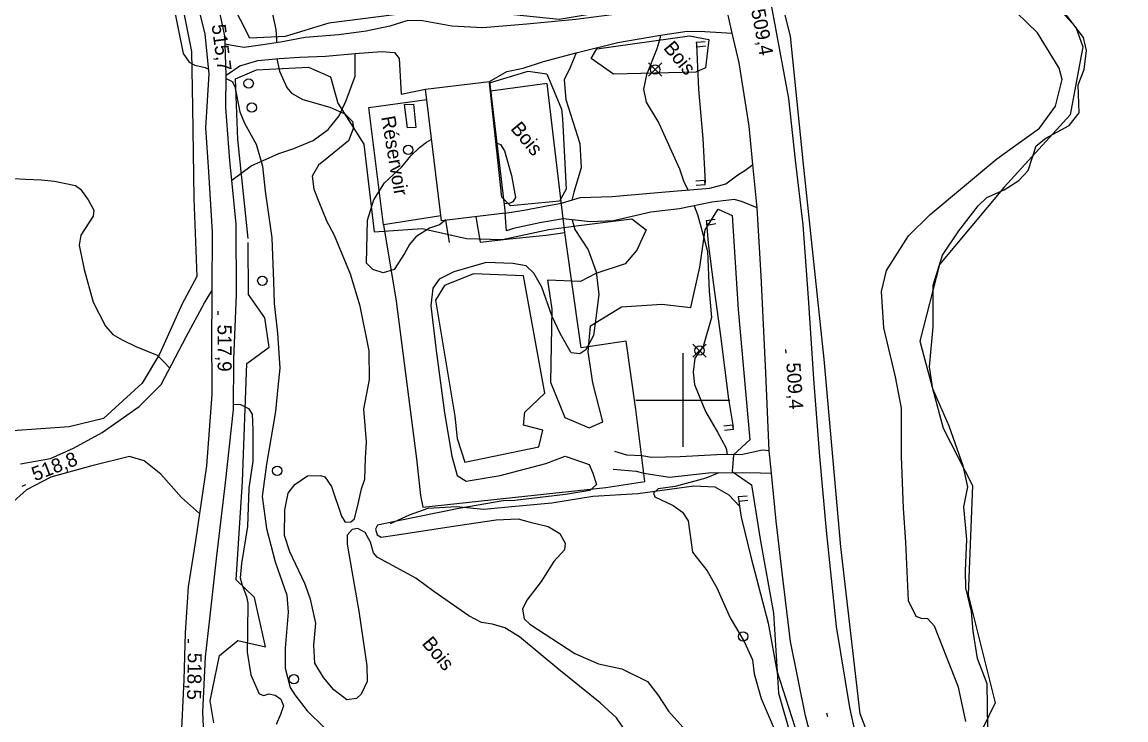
# Model space of a CAD drawing. Extents: x 347312 to 350503, y 6073086 to 6076432.
# Drawn here: x 347759 to 347994.5, y 6075331.8 to 6075480.7 of the extents above; entities that cross this region are included whole.
import ezdxf

# ---------------------------------------------------------------- set-up
doc = ezdxf.new("R2010")
doc.units = 0
for name, color, linetype in [('Level 1', 7, 'Continuous'), ('Level 19', 7, 'Continuous'), ('Level 2', 7, 'Continuous'), ('Level 21', 7, 'Continuous'), ('Level 22', 7, 'Continuous'), ('Level 26', 7, 'Continuous'), ('Level 3', 7, 'Continuous'), ('Level 31', 7, 'Continuous'), ('Level 33', 7, 'Continuous'), ('Level 36', 7, 'Continuous'), ('Level 37', 7, 'Continuous'), ('Level 4', 7, 'Continuous'), ('Level 44', 7, 'Continuous'), ('Level 61', 7, 'Continuous')]:
    doc.layers.add(name, color=color, linetype=linetype)

msp = doc.modelspace()

# ---------------------------------------------------------------- linework, layer by layer
at = {"layer": 'Level 1'}
for points in [[(347895.24, 6075477.89), (347895.1, 6075477.1), (347894.43, 6075474.95), (347892.21, 6075469.37), (347891.63, 6075466.35), (347892.18, 6075463.58), (347894.84, 6075459.07), (347899.29, 6075449.32), (347900.16, 6075446.81), (347901.05, 6075444.85)], [(347902.42, 6075441.44), (347903.12, 6075439.57), (347904.11, 6075435.94), (347905.26, 6075431.69), (347905.6, 6075423.24), (347906.08, 6075417.64), (347904.33, 6075411.47), (347902.54, 6075408.93), (347902.18, 6075405.96), (347902.45, 6075403.36), (347904.85, 6075397.55), (347907.38, 6075393.19), (347909.27, 6075389.78), (347909.42, 6075388.37)], [(347907.65, 6075384.47), (347904.91, 6075383.38), (347898.33, 6075381.6), (347894.75, 6075381.07), (347893.72, 6075380.12), (347894, 6075379.38), (347897.95, 6075377.53), (347899.95, 6075376.08), (347901.1, 6075374.21)], [(347901.1, 6075374.21), (347902.02, 6075367.58), (347905.17, 6075363.6), (347907.26, 6075359.94), (347910.12, 6075353.57), (347913.1, 6075348.5), (347914.87, 6075344.58), (347915.18, 6075341.61), (347916.74, 6075336.32), (347921.63, 6075324.89), (347925.34, 6075314.24), (347927.25, 6075307.21), (347928.36, 6075303.28), (347930.88, 6075297.16), (347931.75, 6075293.98), (347933.88, 6075289.95), (347937.53, 6075284.88), (347946.95, 6075267.18), (347955.97, 6075255.25), (347966.82, 6075242.72), (347972.12, 6075236.76), (347984.59, 6075221.05), (347997.12, 6075207.8)]]:
    msp.add_lwpolyline(points, dxfattribs=at)
at = {"layer": 'Level 19'}
for points in [[(347907.61, 6075488.88), (347904.36, 6075486.65), (347900.4, 6075484.99), (347893.62, 6075483.26), (347887.03, 6075482.45), (347877.15, 6075481.23), (347866.71, 6075480.18), (347857.33, 6075479.46), (347850.72, 6075479.76), (347844.42, 6075480.93), (347841.33, 6075481), (347837.46, 6075479.79), (347832.41, 6075478.71), (347826.57, 6075477.93), (347819.4, 6075477.37), (347814.15, 6075476.34), (347810.41, 6075475.77), (347806.38, 6075475.26), (347804.65, 6075475.51), (347802.36, 6075475.95)], [(347858.72, 6075467.97), (347862.42, 6075470.1), (347865.93, 6075470.85), (347870.29, 6075472.21), (347877.24, 6075474.09), (347886.13, 6075476.28), (347894.81, 6075477.82), (347900.91, 6075478.75), (347904.66, 6075478.63), (347910.54, 6075478.29)], [(347802.56, 6075469.32), (347805.47, 6075471.3), (347809.3, 6075472.47), (347813.89, 6075472.86), (347818.22, 6075473.18), (347823.78, 6075473.41), (347830.05, 6075473.95), (347835.74, 6075474.38), (347838.49, 6075474.17), (347839.45, 6075472.87), (347839.93, 6075465.26), (347845.09, 6075466.34)], [(347915.85, 6075441.03), (347912.71, 6075442.32), (347910.99, 6075442.82), (347906.21, 6075442.2), (347899.29, 6075440.81), (347893.2, 6075440.12), (347885.23, 6075438.28), (347880.2, 6075438.05), (347874.48, 6075438.69), (347869.48, 6075437.81), (347863.89, 6075436.64), (347862.35, 6075436.15), (347862.09, 6075439.89), (347866.09, 6075440.52), (347871.34, 6075441.55), (347874.08, 6075442.03), (347878.08, 6075443.2), (347884.91, 6075443.46), (347896.32, 6075444.47), (347905.76, 6075445.23), (347909.14, 6075446.16), (347911.73, 6075448.09), (347913.23, 6075449), (347914.94, 6075450.29)], [(347758.65, 6075386.44), (347765.06, 6075387.54), (347770.02, 6075389.75), (347776.1, 6075393.11), (347783.97, 6075398.64), (347788.67, 6075403.32), (347794, 6075413.52), (347797.96, 6075420.79), (347799.51, 6075423.35)], [(347918.4, 6075389.21), (347916.91, 6075389.34), (347912.8, 6075388.4), (347907.26, 6075388.36), (347899.44, 6075387.91), (347893.32, 6075387.76), (347891.21, 6075388.14), (347888.03, 6075388.26), (347885.52, 6075389.02)], [(347796.86, 6075375.79), (347793.04, 6075379.23), (347788.59, 6075384.21), (347785.05, 6075387.08), (347781.93, 6075387.97), (347773.59, 6075385.94), (347765.15, 6075383.59), (347759.94, 6075380.85), (347756.46, 6075377.76), (347755.27, 6075375.87), (347755.24, 6075372.5), (347755.73, 6075367.08)], [(347885.1, 6075385.29), (347890.01, 6075384.81), (347891.69, 6075384.41), (347897.18, 6075383.59), (347905.5, 6075384.45), (347912.8, 6075384.53), (347916.53, 6075384.49), (347918.88, 6075384.39)]]:
    msp.add_lwpolyline(points, dxfattribs=at)
at = {"layer": 'Level 2'}
for points in [[(347773.24, 6075516.51), (347773.72, 6075514.64), (347775.84, 6075511.59), (347777.97, 6075509.35), (347782.93, 6075505.44), (347786.21, 6075500.82), (347787.56, 6075498.07), (347789.34, 6075492.21), (347791.05, 6075485.62), (347793.38, 6075473.95), (347794.67, 6075472.07), (347795.85, 6075471.45), (347798.09, 6075470.96)], [(347811.88, 6075484.95), (347813.15, 6075479.05), (347813.27, 6075477.12), (347813.28, 6075476.21)], [(347960.39, 6075331.46), (347958.79, 6075338.76), (347953.66, 6075351.77), (347952.26, 6075353.31), (347950.94, 6075353.44), (347949.8, 6075353.84), (347948.12, 6075357.17), (347947.6, 6075369.66), (347947.1, 6075376.92), (347946.67, 6075387.99), (347946.61, 6075398.3), (347945.4, 6075404.96), (347942.91, 6075415.43), (347942.39, 6075423.2), (347943.41, 6075427.66), (347948.17, 6075435.07), (347952.73, 6075439.62), (347967, 6075451.47), (347976.11, 6075458.02), (347979.51, 6075462.69), (347980.94, 6075468.43), (347980.28, 6075470.85), (347975.67, 6075478.36), (347968.9, 6075484.9)], [(347877.24, 6075474.09), (347877.24, 6075474.09), (347875.97, 6075470.93), (347874.67, 6075468.34), (347875.02, 6075464.13), (347878.02, 6075454.77), (347878.29, 6075449.58), (347876.75, 6075444.39), (347876.33, 6075442.69)], [(347813.37, 6075472.81), (347813.93, 6075470.21), (347815.5, 6075466.7), (347816.48, 6075465.51), (347818.92, 6075464.17), (347824.7, 6075462.52), (347827.86, 6075461.11), (347829.53, 6075459.41), (347829.7, 6075458.08), (347828.63, 6075455.34), (347824.5, 6075451.94), (347822.27, 6075450.11), (347820.88, 6075447.76), (347821.28, 6075445.02), (347822.34, 6075442.28), (347823.88, 6075438.48)], [(347798.09, 6075470.96), (347798.77, 6075470.61)], [(347802.55, 6075468.63), (347803.85, 6075467.95), (347804.41, 6075466.9), (347805.51, 6075461.54), (347806.45, 6075459.11), (347808.95, 6075454.64), (347810.32, 6075449.91), (347810.85, 6075444.61)], [(347849.42, 6075438.47), (347848.11, 6075437.43), (347845.92, 6075436.7), (347843.03, 6075434.86), (347841.7, 6075433.23), (347840.64, 6075431.29), (347838.43, 6075427.9), (347836.05, 6075427.14), (347833.83, 6075427.88), (347832.51, 6075429.25), (347832.75, 6075438.4), (347834.1, 6075442.74), (347836.35, 6075446.33), (347836.35, 6075446.33), (347840.04, 6075449.77), (347841.96, 6075452.14), (347843.81, 6075453.93), (347845.31, 6075455.03), (347846.29, 6075455.61)], [(347860, 6075454.95), (347861.09, 6075454.52), (347861.92, 6075453.19), (347863.47, 6075447.93), (347864.28, 6075443.24), (347863.75, 6075442.27), (347863.14, 6075442.04), (347861.77, 6075441.9)], [(347757.12, 6075447.26), (347759.73, 6075447.15), (347763.07, 6075446.97), (347765.96, 6075446.68), (347770.4, 6075445.81), (347771.48, 6075444.98), (347773.09, 6075442.71), (347774.35, 6075440.55), (347774.22, 6075439.25), (347771.58, 6075435.21), (347771.23, 6075433.06), (347772.27, 6075427.9), (347774.2, 6075420.89), (347776.82, 6075415.8), (347778.36, 6075413.97), (347780.4, 6075412.83), (347783.31, 6075411.47), (347787.82, 6075409.59), (347789.29, 6075408.14), (347790.51, 6075406.84)], [(347810.85, 6075444.61), (347812.31, 6075434.61), (347812.67, 6075425.31), (347812.81, 6075420.63), (347813.53, 6075414.28), (347813.99, 6075406.79), (347813.6, 6075402.74), (347813.11, 6075397.54), (347811.17, 6075386.34), (347810.22, 6075379.43), (347811.2, 6075372.62), (347813.05, 6075365.53), (347815.49, 6075358.39), (347815.81, 6075354.75), (347815.15, 6075347.08), (347815.18, 6075342.81), (347816.2, 6075338.66), (347817.24, 6075337.1), (347819.81, 6075333.7), (347823.49, 6075330.12)], [(347828.31, 6075336.02), (347825.54, 6075338.19), (347823.33, 6075340.82), (347821.46, 6075343.87), (347821.24, 6075347.72), (347821.69, 6075352.4), (347820.54, 6075357.52), (347819.37, 6075360.88), (347816.14, 6075367.6), (347815, 6075371.08), (347815.09, 6075376.62), (347815.79, 6075380.14), (347817.21, 6075381.97), (347819.95, 6075383.82), (347822.67, 6075383.92), (347823.59, 6075383.61), (347825.01, 6075381.57), (347827.19, 6075375.21), (347827.95, 6075373.97), (347829.13, 6075374), (347829.92, 6075374.65), (347830.77, 6075378.15), (347831.41, 6075381.09), (347832.12, 6075383.14), (347832.32, 6075387.58), (347832.5, 6075391.07), (347831.92, 6075398.07), (347833.11, 6075404.39), (347833.1, 6075410.53), (347831.14, 6075420.01), (347831.14, 6075420.01), (347829.1, 6075426.89), (347825.65, 6075435.14), (347823.88, 6075438.48)], [(347876.36, 6075438.48), (347876.93, 6075436.43), (347879.81, 6075432.08), (347881.51, 6075427.34), (347882.06, 6075422.54), (347881.44, 6075417.51), (347880.93, 6075413.79), (347879.27, 6075410.74), (347878.04, 6075409.87), (347876.18, 6075410.12), (347873.84, 6075414.18), (347872.13, 6075417.85), (347869.92, 6075424.11), (347868.22, 6075427.05), (347866.56, 6075428.67), (347863.74, 6075429.17), (347858.03, 6075429.35), (347851.13, 6075427.35)], [(347851.13, 6075427.35), (347848.04, 6075425.82), (347846.64, 6075423.9), (347846.21, 6075420.08), (347847.4, 6075410.56), (347849.14, 6075397.29), (347850.68, 6075388.06), (347851.86, 6075383.94), (347853.79, 6075382.71), (347861.03, 6075383.94), (347870.76, 6075386.51), (347874.91, 6075388.03), (347879.99, 6075386.26), (347880.8, 6075384.39), (347881.57, 6075382.03), (347880.14, 6075380.68), (347874.98, 6075379.83), (347864.14, 6075378.59), (347861.67, 6075378.5)], [(347804.14, 6075399.15), (347805.65, 6075399.07), (347807.33, 6075398.21), (347808.09, 6075396.97), (347808.28, 6075393.67), (347808.23, 6075386.97), (347807.4, 6075381.22), (347807.1, 6075373.01), (347805.82, 6075365.11), (347805.52, 6075362.05), (347805.97, 6075360.54), (347806.93, 6075358.1), (347807.16, 6075356.68), (347807.11, 6075350.73), (347807.05, 6075346.25), (347807.85, 6075341.4), (347809.61, 6075337.35), (347810.61, 6075336.96), (347811.69, 6075337.3), (347813, 6075337.04), (347814.25, 6075336.19), (347814.78, 6075334.74), (347814.16, 6075332.89), (347813.21, 6075330.77)], [(347861.67, 6075378.5), (347861.67, 6075378.5), (347852.19, 6075376.87), (347839.24, 6075374.26), (347834.82, 6075373.3), (347834.44, 6075372.46), (347834.77, 6075371.26), (347835.6, 6075370.73), (347838.58, 6075371.17), (347851.99, 6075373.22), (347860.19, 6075374.47), (347864.84, 6075374.67), (347867.42, 6075373.98), (347871.29, 6075373.01), (347873.72, 6075371.53), (347874.86, 6075369.51)], [(347889.18, 6075327.32), (347885.83, 6075332.19), (347882.39, 6075335.39), (347873.52, 6075342.56), (347865.15, 6075349.46), (347862.04, 6075351.45), (347859.4, 6075352.22), (347857.01, 6075352.53), (347854.35, 6075353.96), (347846.85, 6075359.16), (347843.02, 6075362.03), (347834.79, 6075366.49), (347834, 6075367.45), (347833.34, 6075369.71), (347832.21, 6075371.72), (347830.68, 6075372.6), (347829.41, 6075372.36), (347828.35, 6075371.22), (347828.38, 6075369.25), (347829.38, 6075363.52), (347830.84, 6075354.96), (347832.59, 6075343.3), (347832.64, 6075339.98), (347831.34, 6075337.29), (347830.36, 6075336.35), (347828.31, 6075336.02)], [(347874.86, 6075369.51), (347874.72, 6075368.06), (347872.5, 6075365.56), (347869.74, 6075361.29), (347866.72, 6075357.34), (347865.8, 6075355.38), (347866.13, 6075353.37), (347867.34, 6075352.22), (347876.96, 6075345.92), (347881.97, 6075343.74), (347887.01, 6075342.66), (347892.42, 6075340), (347894.65, 6075337.14), (347896.9, 6075333.62), (347899.96, 6075330.24)]]:
    msp.add_lwpolyline(points, dxfattribs=at)
at = {"layer": 'Level 21'}
for points in [[(347794.69, 6075491.63), (347797.98, 6075478.11), (347798.88, 6075469.58), (347798.13, 6075458.12), (347798.76, 6075448.68), (347799.57, 6075435.85), (347799.51, 6075423.35), (347799.49, 6075419.76), (347799.41, 6075414.85), (347799.48, 6075401.23), (347798.38, 6075385.96), (347796.86, 6075375.79), (347796, 6075370), (347794.45, 6075360.19), (347793.85, 6075350.35), (347793.55, 6075340.31), (347792.84, 6075325.38)], [(347798.08, 6075322.78), (347797.62, 6075333.45), (347798.16, 6075345.26), (347799.06, 6075353.33), (347800.56, 6075366.77), (347802.42, 6075382.37), (347804.13, 6075397.99), (347804.2, 6075408.67), (347804.75, 6075422.51), (347804.7, 6075437.51), (347803.75, 6075446.92), (347803.33, 6075451.08), (347802.49, 6075462.45), (347802.56, 6075469.32), (347802.36, 6075475.95), (347802.3, 6075477.72), (347799.98, 6075488.36)], [(347997.16, 6075234.9), (347986.45, 6075247.11), (347977.66, 6075258.45), (347969.58, 6075269.85), (347962.2, 6075279.88), (347955.46, 6075289.76), (347950.45, 6075297.85), (347946.32, 6075305.24), (347941.2, 6075316.25), (347937, 6075328.23), (347935.59, 6075334.4), (347932.81, 6075351.71), (347930.64, 6075372.21), (347929.21, 6075387.95), (347927.96, 6075404.53), (347926.82, 6075421.8), (347925.66, 6075437.39), (347924.05, 6075451.21), (347922.63, 6075464.36), (347918.91, 6075484.27)], [(347997.62, 6075218.41), (347983.78, 6075234.65), (347971.18, 6075249.57), (347962.21, 6075260.23), (347954.87, 6075270.21), (347945.69, 6075285.36), (347938.68, 6075298.1), (347933.96, 6075307.55), (347929.65, 6075319.22), (347926.19, 6075332.66), (347922.95, 6075348.47), (347921.38, 6075361.45), (347919.91, 6075374.14), (347918.88, 6075384.39), (347918.4, 6075389.21), (347917.7, 6075405.85), (347916.74, 6075426.5), (347915.85, 6075441.03), (347914.94, 6075450.29), (347914.15, 6075458.42), (347912.01, 6075471.99), (347910.54, 6075478.29), (347909.51, 6075482.76)]]:
    msp.add_lwpolyline(points, dxfattribs=at)
at = {"layer": 'Level 22'}
msp.add_lwpolyline([(347803.75, 6075446.92), (347807.89, 6075450.02), (347813.81, 6075452.63), (347817.02, 6075453.65), (347821.1, 6075455.41), (347824.33, 6075457.74), (347826.67, 6075460.66), (347828.17, 6075463.93), (347830.11, 6075469.08), (347830.05, 6075473.95)], dxfattribs=at)
at = {"layer": 'Level 26'}
for p, q in [((347902.87, 6075476.35), (347904.78, 6075476.53)), ((347902.87, 6075476.35), (347902.97, 6075475.37)), ((347902.97, 6075475.37), (347904.88, 6075475.58)), ((347904.72, 6075446.88), (347902.8, 6075446.74)), ((347904.79, 6075445.9), (347902.87, 6075445.78)), ((347904.79, 6075445.9), (347904.72, 6075446.88)), ((347905, 6075438.33), (347906.89, 6075438.62)), ((347905, 6075438.33), (347905.16, 6075437.36)), ((347905.16, 6075437.36), (347907.05, 6075437.67)), ((347910.66, 6075394.69), (347908.75, 6075394.44)), ((347910.79, 6075393.72), (347910.66, 6075394.69)), ((347910.79, 6075393.72), (347908.88, 6075393.49)), ((347911.83, 6075379.41), (347913.74, 6075379.61)), ((347911.83, 6075379.41), (347911.94, 6075378.44)), ((347911.94, 6075378.44), (347913.85, 6075378.65))]:
    msp.add_line(p, q, dxfattribs=at)
at = {"layer": 'Level 3'}
for p, q in [((347800.75, 6075418.99), (347800.75, 6075418.19)), ((347921.91, 6075410.8), (347921.97, 6075410)), ((347759.07, 6075381.67), (347759.82, 6075381.96)), ((347794.47, 6075349), (347794.45, 6075348.2)), ((347930.65, 6075333.29), (347930.87, 6075332.52))]:
    msp.add_line(p, q, dxfattribs=at)
at = {"layer": 'Level 31'}
msp.add_lwpolyline([(347848.47, 6075438.25), (347845.09, 6075466.34), (347858.72, 6075467.97), (347862.09, 6075439.89), (347848.47, 6075438.25)], dxfattribs=at)
at = {"layer": 'Level 33'}
msp.add_lwpolyline([(347842.51, 6075463.17), (347843, 6075458.18), (347841.28, 6075458.09), (347840.58, 6075463.05), (347842.51, 6075463.17)], dxfattribs=at)
at = {"layer": 'Level 36'}
for p, q in [((347892.68, 6075469.11), (347895.5, 6075471.93)), ((347892.68, 6075471.93), (347895.5, 6075469.11)), ((347902.16, 6075409.15), (347904.98, 6075411.97)), ((347902.16, 6075411.97), (347904.98, 6075409.15))]:
    msp.add_line(p, q, dxfattribs=at)
msp.add_lwpolyline([(347850.21, 6075433.61), (347849.4, 6075438.37)], dxfattribs=at)
for centre in [(347894.09, 6075470.52), (347807.36, 6075467.58), (347808.02, 6075462.41), (347841.4, 6075453.4), (347810.28, 6075425.46), (347903.57, 6075410.56), (347813.46, 6075384.93), (347912.85, 6075349.58), (347817.01, 6075340.44)]:
    msp.add_circle(centre, 1, dxfattribs=at)
at = {"layer": 'Level 37'}
for points in [[(347836.16, 6075437.42), (347838.82, 6075421.1), (347843.16, 6075387.5), (347843.99, 6075379.66), (347844.53, 6075377.15), (347866.28, 6075379.5), (347883.58, 6075381.35), (347891.92, 6075382.61), (347889.96, 6075398.01), (347887.93, 6075412.6), (347878.27, 6075411.13), (347876.16, 6075426.17), (347874.82, 6075435.78), (347872.42, 6075456.11), (347871.04, 6075467.56), (347858.96, 6075465.94)], [(347848.34, 6075439.29), (347836.16, 6075437.42), (347833, 6075462.45), (347845.36, 6075464.12)], [(347855.81, 6075439.13), (347856.72, 6075433.67), (347863.04, 6075434.42), (347870.87, 6075435.2), (347874.82, 6075435.78)]]:
    msp.add_lwpolyline(points, dxfattribs=at)
at = {"layer": 'Level 4'}
for points in [[(347965.07, 6075330.04), (347964.9, 6075339.47), (347962.89, 6075344.87), (347961.94, 6075350.71), (347961.58, 6075354.93), (347960.4, 6075359.97), (347960.31, 6075363.6), (347960.55, 6075370.28), (347959.91, 6075377.2), (347960.79, 6075381.48), (347959.8, 6075386.01), (347956.83, 6075394.46), (347953.32, 6075402.38), (347952.63, 6075407.08), (347953.41, 6075415.65), (347953.4, 6075424.53), (347955.41, 6075430.89), (347958.85, 6075436.09), (347962.99, 6075441.44), (347964.88, 6075443.24), (347968.52, 6075444.85), (347971.66, 6075446.87), (347973.66, 6075449), (347975.41, 6075454.23), (347977.42, 6075455.9), (347982.43, 6075458.58), (347984.56, 6075461.26), (347984.37, 6075467.28), (347985.65, 6075470.54), (347986.14, 6075474.57), (347985.45, 6075477.39), (347980.94, 6075483.34)], [(347902.9, 6075475.85), (347903.37, 6075466.26), (347904.26, 6075455.84), (347904.77, 6075446.4)], [(347905.06, 6075437.83), (347905.43, 6075433.5), (347906.56, 6075424.58), (347908.05, 6075413.73), (347909.76, 6075400.23), (347910.74, 6075394.22)], [(347837.6, 6075373.65), (347841.65, 6075375.54), (347845.66, 6075376.94), (347851.67, 6075377.31), (347857.55, 6075376.74), (347863.54, 6075377.31), (347872.05, 6075378.11), (347880.82, 6075379.5), (347890.37, 6075380.04), (347902.37, 6075381.71), (347906.83, 6075381.52), (347909.83, 6075379.81), (347912.11, 6075377.34)], [(347911.87, 6075378.91), (347912.11, 6075377.34), (347912.44, 6075375.06), (347914.51, 6075366.54), (347918.23, 6075352.39), (347920.03, 6075342.22), (347924.54, 6075328.29), (347927.85, 6075318.59), (347932.35, 6075307.77), (347935.71, 6075300.34)]]:
    msp.add_lwpolyline(points, dxfattribs=at)
at = {"layer": 'Level 44'}
for points in [[(347842.82, 6075729.01), (347844.18, 6075728.01), (347849.05, 6075708.18), (347845.71, 6075683.42), (347836.37, 6075667.79), (347837.43, 6075658.07), (347848.38, 6075647.42), (347858.75, 6075626.84), (347866.86, 6075615.27), (347872.31, 6075607.49), (347882.47, 6075594.94), (347891.73, 6075583.44), (347902.22, 6075570.87), (347909.42, 6075560.34), (347917.51, 6075550.56), (347926.66, 6075544.14), (347944.37, 6075523.49), (347963.94, 6075501.4), (347983.85, 6075479.6), (347985.33, 6075475.4), (347982.61, 6075460.88), (347968.54, 6075445.42), (347954.73, 6075428.96), (347950.56, 6075412.59)], [(347950.56, 6075412.59), (347955.53, 6075394.04), (347961.8, 6075381.79), (347960.86, 6075358.45), (347966.64, 6075335.42), (347956.96, 6075315.59), (347954.08, 6075303.85), (347948.34, 6075305.68), (347937.86, 6075333.06), (347933.71, 6075368.72), (347930.13, 6075408.75), (347925.81, 6075449.66), (347922.94, 6075477.65), (347915.36, 6075508.03), (347894.9, 6075549.01), (347872.97, 6075582.7), (347845.07, 6075625.82), (347811.9, 6075672.62), (347799.3, 6075693.06)], [(347803.22, 6075484.95), (347800.36, 6075507.09), (347799.21, 6075524.04), (347802.38, 6075531.6), (347811.25, 6075534.99), (347827.17, 6075528.41), (347832.52, 6075526.05), (347841.24, 6075536.88), (347838.49, 6075542.55), (347840.94, 6075545.87), (347861.58, 6075552.86), (347872.3, 6075551.14), (347878.92, 6075544.84), (347889.65, 6075523.84), (347903.4, 6075496.32), (347903.35, 6075489.14), (347896.18, 6075484.94), (347873.63, 6075481.18), (347858.36, 6075482.74), (347845.11, 6075483.02), (347824.49, 6075480.42), (347815.16, 6075477.55), (347807.58, 6075477.21), (347803.6, 6075485.04)], [(347754.2, 6075548.47), (347761.49, 6075548.24), (347765.82, 6075546.53), (347769.99, 6075541.5), (347779.42, 6075531.92), (347785.72, 6075520.7), (347791.27, 6075493.91), (347795.14, 6075474.41), (347795.38, 6075462.59), (347795.63, 6075443.05), (347796.28, 6075426.34), (347793.16, 6075420.54), (347788.37, 6075409.82), (347784.67, 6075403.59), (347776.38, 6075396.06), (347769.1, 6075394.31), (347756.97, 6075393.42)], [(347902.8, 6075469.95), (347885.22, 6075469.55), (347880.45, 6075472.92), (347881.62, 6075474.95), (347901.45, 6075477.69), (347905.56, 6075476.91), (347904.85, 6075470.9), (347902.8, 6075469.95)], [(347807.24, 6075434.5), (347805.02, 6075455.58), (347804.52, 6075468.55), (347809.05, 6075470.48), (347820.16, 6075471.04), (347824.81, 6075468.98), (347826.38, 6075463.32), (347831.9, 6075454.59), (347834.15, 6075435.92), (347844.41, 6075436.63), (347853.85, 6075434.45), (347861.45, 6075434.26), (347871.41, 6075436.42), (347877.77, 6075437.26), (347889.12, 6075438.69), (347892.14, 6075436.3), (347890.16, 6075432), (347887.67, 6075429.08), (347881.4, 6075427.02), (347878.17, 6075425.31), (347871.11, 6075425.6), (347872.03, 6075419.41), (347871.75, 6075403.83), (347874.85, 6075396.32), (347879.98, 6075394.06), (347882.93, 6075395.39), (347880.79, 6075403.71), (347879.79, 6075410.31), (347880.31, 6075415.87), (347886.9, 6075419.91), (347895.5, 6075420.48), (347901.73, 6075419.77), (347903.6, 6075428.37), (347904.77, 6075436.36), (347907.55, 6075440.75), (347910.54, 6075439.36), (347911.81, 6075419.32), (347914.28, 6075391.51), (347910.78, 6075388.34), (347910.51, 6075384.77), (347914.61, 6075381.93), (347916.57, 6075369.92), (347919.32, 6075354.51), (347920.38, 6075337.46), (347928.18, 6075310.43)], [(347874.34, 6075460.01), (347875.11, 6075445.04), (347873.65, 6075442.47), (347863.25, 6075441.43), (347861.38, 6075443.32), (347858.77, 6075467.67), (347867.01, 6075470.21), (347870.96, 6075469.61), (347874.12, 6075462.05), (347874.34, 6075460.01)], [(347799.96, 6075331.13), (347799.17, 6075335.84), (347801.11, 6075345.53), (347805.06, 6075348.68), (347810.96, 6075347.33), (347808.58, 6075357.9), (347804.69, 6075361.67), (347806.02, 6075382.65), (347807, 6075407.83), (347811.72, 6075411.32), (347810.82, 6075417.59), (347807.35, 6075422.56), (347807.28, 6075433.62)], [(347851.84, 6075391.83), (347853.51, 6075386.76), (347869.3, 6075390.02), (347870.11, 6075393.56), (347866.03, 6075394.66), (347866.28, 6075397.43), (347870.58, 6075401.47), (347865.97, 6075426.48), (347855.36, 6075426.94), (347849.15, 6075424.46), (347847.23, 6075421.35), (347851.37, 6075396.55), (347851.84, 6075391.83)]]:
    msp.add_lwpolyline(points, dxfattribs=at)
at = {"layer": 'Level 61'}
for p, q in [((347900, 6075410), (347900, 6075390)), ((347890, 6075400), (347910, 6075400))]:
    msp.add_line(p, q, dxfattribs=at)

# ---------------------------------------------------------------- texts
at = {"layer": 'Level 3'}
for s, rotation, p in [('509,4', 280.5764, (347914.55, 6075483.19)), ('515,7', 277.6017, (347799.45, 6075480.01)), ('517,9', 270.0984, (347800.72, 6075416.11)), ('509,4', 273.7686, (347922.07, 6075407.92)), ('518,8', 21.0318, (347761.77, 6075382.67)), ('518,5', 269.0004, (347794.38, 6075346.12))]:
    msp.add_text(s, height=3, rotation=rotation, dxfattribs=at).set_placement(p)
at = {"layer": 'Level 33'}
msp.add_text('Réservoir', height=3, rotation=279.5804, dxfattribs=at).set_placement((347835.63, 6075460.4))
at = {"layer": 'Level 44'}
for p in [(347895.72, 6075475.07), (347863.1, 6075457.86), (347844.19, 6075348.02)]:
    msp.add_text('Bois', height=3, rotation=309.568, dxfattribs=at).set_placement(p)

doc.saveas('drawing.dxf')
